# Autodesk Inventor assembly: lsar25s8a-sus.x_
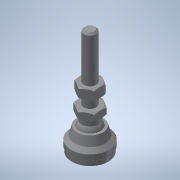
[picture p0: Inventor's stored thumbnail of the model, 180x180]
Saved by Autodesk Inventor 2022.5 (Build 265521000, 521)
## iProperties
Part Number: lsar25s8a-sus.x_
Material: 一般
Document SubType Name: Assembly
Designer: ImaoCorp
Sending System: SOLIDWORKS 2017-2017317
MC: AMD64
MC_MODEL: Intel64 Family 6 Model 60 Stepping 3, GenuineIntel
OS: Windows_NT
FRU: Parasolid Version 29.0, build 201,  4-17-2017
FORMAT: text
GUISE: transmit
KEY: lsar25s8a-sus
FILE: lsar25s8a-sus.x_t
DATE: Mon Jul 01 17:59:54 2019
Author: ImaoCorp
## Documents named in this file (3)
- X:\14_SW2022-Inv2022\00_全2023-1023新製品(TCC)まで\l\lsar25s8a-sus\LSAR25S8A-SUS.iam
- X:\14_SW2022-Inv2022\00_全2023-1023新製品(TCC)まで\l\lsar25s8a-sus\lsar25s8a-sus_01.ipt
- X:\14_SW2022-Inv2022\00_全2023-1023新製品(TCC)まで\l\lsar25s8a-sus\lsar25s8a-sus_02.ipt
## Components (2 placed, 2 different names)
1. lsar25s8a-sus_01
2. lsar25s8a-sus_02
